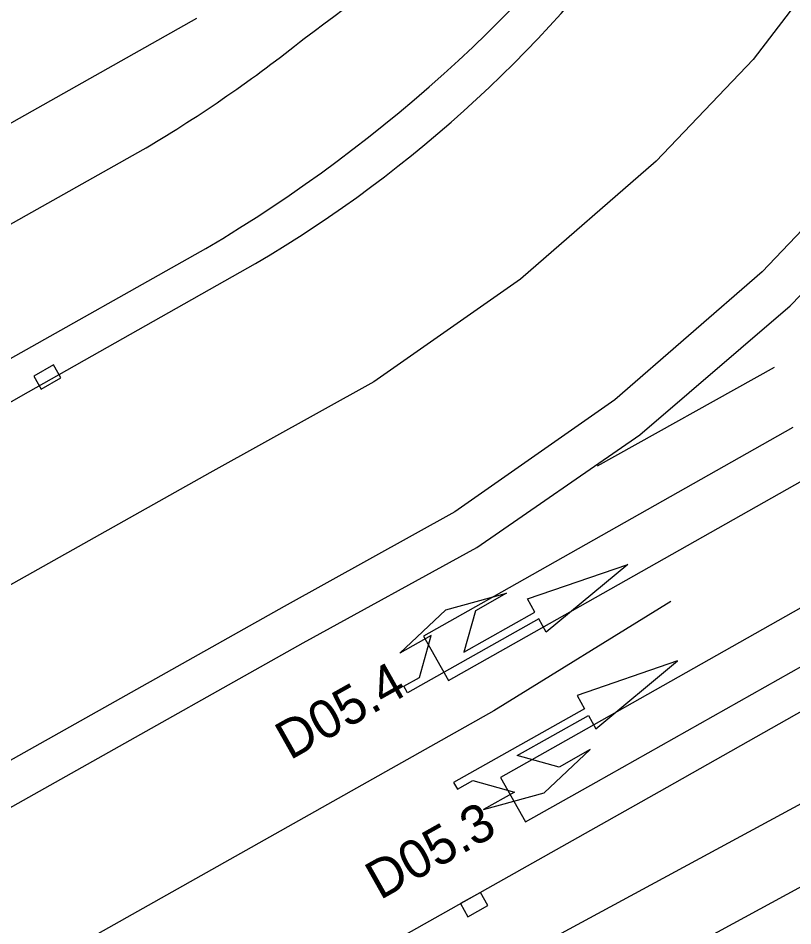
# Model space of a CAD drawing. Extents: x 81065 to 81486, y 452384 to 452681.
# Drawn here: x 81194.78 to 81209.97, y 452476.31 to 452494.11 of the extents above; entities that cross this region are included whole.
import ezdxf

# ---------------------------------------------------------------- set-up
doc = ezdxf.new("R2010")
doc.units = 0
for name, color, linetype in [('B-BH-VH-KANTOPSLUITING-GV', 7, 'Continuous'), ('B-SB-OG-WEG_SPOOR_TRAM-G', 7, 'Continuous'), ('B-SRI-KOLK_COMBINATIE-S', 7, 'Continuous'), ('B-WE-VW-MARKERING_LANGS_STREEP_13_010-G', 7, 'Continuous'), ('B-WE-VW-MARKERING_LANGS_STREEP_13_030-G', 7, 'Continuous'), ('B-WE-VW-MARKERING_PIJL-S', 7, 'Continuous'), ('N-OI-KL-VRI_LUS_DETECTIE-G', 7, 'Continuous'), ('N-OI-KL-VRI_LUS_DETECTIE-T18', 7, 'Continuous')]:
    doc.layers.add(name, color=color, linetype=linetype)

msp = doc.modelspace()

# ---------------------------------------------------------------- linework, layer by layer
at = {"layer": 'B-BH-VH-KANTOPSLUITING-GV'}
for p, q in [((81152.64, 452466.443), (81197.33, 452491.595)), ((81153.769, 452464.439), (81198.458, 452489.59))]:
    msp.add_line(p, q, dxfattribs=at)
for points in [[(81215.184, 452496.736), (81213.682, 452494.242), (81211.474, 452491.348), (81209.365, 452489.136), (81206.477, 452486.625), (81203.342, 452484.43), (81199.995, 452482.573), (81157.091, 452458.458), (81156.072, 452457.868), (81151.131, 452454.729), (81146.282, 452451.196), (81140.808, 452446.932)], [(81141.843, 452446.719), (81147.942, 452451.449), (81151.636, 452454.16), (81156.157, 452457.017), (81157.59, 452457.827), (81191.478, 452476.863), (81200.364, 452481.854), (81203.771, 452483.726), (81206.967, 452485.937), (81209.919, 452488.465), (81212.154, 452490.776), (81214.522, 452493.647), (81216.352, 452496.426)], [(81198.272, 452494.107), (81193.157, 452491.223)], [(81137.719, 452452.145), (81138.55, 452452.826), (81141.8, 452455.408), (81147.496, 452459.526), (81153.416, 452463.313), (81186.456, 452481.904), (81194.83, 452486.694), (81199.429, 452489.297)], [(81220.335, 452486.293), (81217.165, 452484.447), (81214.437, 452482.941), (81207.347, 452478.935), (81194.35, 452471.616), (81162.041, 452453.42), (81156.047, 452449.726), (81150.272, 452445.697), (81149.556, 452445.135)]]:
    msp.add_lwpolyline(points, dxfattribs=at)
for centre, radius, start, end in [((81186.921, 452512.487), 23.103, 305.6402, 324.7304), ((81183.359, 452515.018), 29.573, 300.701, 324.6739), ((81186.621, 452511.068), 25.259, 300.4691, 325.0298), ((81183.359, 452515.018), 27.273, 300.701, 308.6243)]:
    msp.add_arc(centre, radius, start, end, dxfattribs=at)
at = {"layer": 'B-SB-OG-WEG_SPOOR_TRAM-G'}
for p, q in [((81250, 452500.286), (81195.496, 452470.783)), ((81250, 452498.654), (81196.18, 452469.521))]:
    msp.add_line(p, q, dxfattribs=at)
at = {"layer": 'B-SRI-KOLK_COMBINATIE-S'}
for p, q in [((81195.469, 452487.309), (81195.08, 452487.087)), ((81195.615, 452487.053), (81195.469, 452487.309)), ((81195.08, 452487.087), (81195.227, 452486.831)), ((81195.227, 452486.831), (81195.615, 452487.053)), ((81203.842, 452476.962), (81203.452, 452476.742)), ((81203.987, 452476.704), (81203.842, 452476.962)), ((81203.452, 452476.742), (81203.597, 452476.485)), ((81203.597, 452476.485), (81203.987, 452476.704))]:
    msp.add_line(p, q, dxfattribs=at)
at = {"layer": 'B-WE-VW-MARKERING_LANGS_STREEP_13_010-G'}
for points in [[(81212.614, 452498.284), (81211.197, 452495.931), (81209.189, 452493.299), (81207.291, 452491.308), (81204.627, 452488.992), (81201.75, 452486.977), (81198.532, 452485.192), (81155.604, 452461.064), (81154.515, 452460.433), (81149.442, 452457.21), (81144.476, 452453.592), (81136.944, 452447.725)], [(81207.574, 452482.668), (81204.107, 452480.525), (81158.751, 452454.982), (81152.636, 452451.213), (81149.732, 452449.187)]]:
    msp.add_lwpolyline(points, dxfattribs=at)
at = {"layer": 'B-WE-VW-MARKERING_LANGS_STREEP_13_030-G'}
msp.add_line((81209.6, 452487.261), (81206.134, 452485.321), dxfattribs=at)
at = {"layer": 'B-WE-VW-MARKERING_PIJL-S'}
for p, q in [((81204.764, 452482.718), (81206.734, 452483.397)), ((81206.734, 452483.397), (81205.132, 452482.064)), ((81203.162, 452482.504), (81204.355, 452482.832)), ((81204.355, 452482.832), (81203.745, 452482.488)), ((81204.911, 452482.456), (81204.764, 452482.718)), ((81202.264, 452481.654), (81203.162, 452482.504)), ((81203.745, 452482.488), (81203.517, 452481.671)), ((81203.517, 452481.671), (81204.911, 452482.456)), ((81204.985, 452482.325), (81202.414, 452480.878)), ((81205.132, 452482.064), (81204.985, 452482.325)), ((81202.874, 452481.998), (81202.264, 452481.654)), ((81202.646, 452481.18), (81202.874, 452481.998)), ((81207.709, 452481.504), (81205.739, 452480.825)), ((81206.107, 452480.171), (81207.709, 452481.504)), ((81202.341, 452481.009), (81202.646, 452481.18)), ((81202.414, 452480.878), (81202.341, 452481.009)), ((81205.739, 452480.825), (81205.886, 452480.563)), ((81205.886, 452480.563), (81203.315, 452479.116)), ((81204.565, 452479.648), (81205.959, 452480.433)), ((81205.959, 452480.433), (81206.107, 452480.171)), ((81205.094, 452478.912), (81205.992, 452479.763)), ((81205.992, 452479.763), (81205.383, 452479.419)), ((81205.383, 452479.419), (81204.565, 452479.648)), ((81203.389, 452478.985), (81203.694, 452479.157)), ((81203.694, 452479.157), (81204.511, 452478.928)), ((81203.315, 452479.116), (81203.389, 452478.985)), ((81204.511, 452478.928), (81203.901, 452478.585)), ((81203.901, 452478.585), (81205.094, 452478.912))]:
    msp.add_line(p, q, dxfattribs=at)
at = {"layer": 'N-OI-KL-VRI_LUS_DETECTIE-G'}
for p, q in [((81202.724, 452481.99), (81203.215, 452481.119)), ((81203.215, 452481.119), (81203.215, 452481.119)), ((81204.237, 452479.215), (81204.728, 452478.344)), ((81204.728, 452478.344), (81204.728, 452478.344))]:
    msp.add_line(p, q, dxfattribs=at)
for points in [[(81209.969, 452486.081), (81204.105, 452482.768), (81202.724, 452481.99)], [(81203.215, 452481.119), (81204.597, 452481.897), (81210.461, 452485.21)], [(81211.481, 452483.306), (81205.618, 452479.993), (81204.237, 452479.215)], [(81204.728, 452478.344), (81206.109, 452479.122), (81211.973, 452482.435)]]:
    msp.add_lwpolyline(points, dxfattribs=at)

# ---------------------------------------------------------------- texts
at = {"layer": 'N-OI-KL-VRI_LUS_DETECTIE-T18'}
for s, rotation, p in [('D05.4', 29.3869, (81200.106, 452479.547)), ('D05.3', 29.3852, (81201.872, 452476.803))]:
    msp.add_text(s, height=0.75, rotation=rotation, dxfattribs=at).set_placement(p)

doc.saveas('drawing.dxf')
